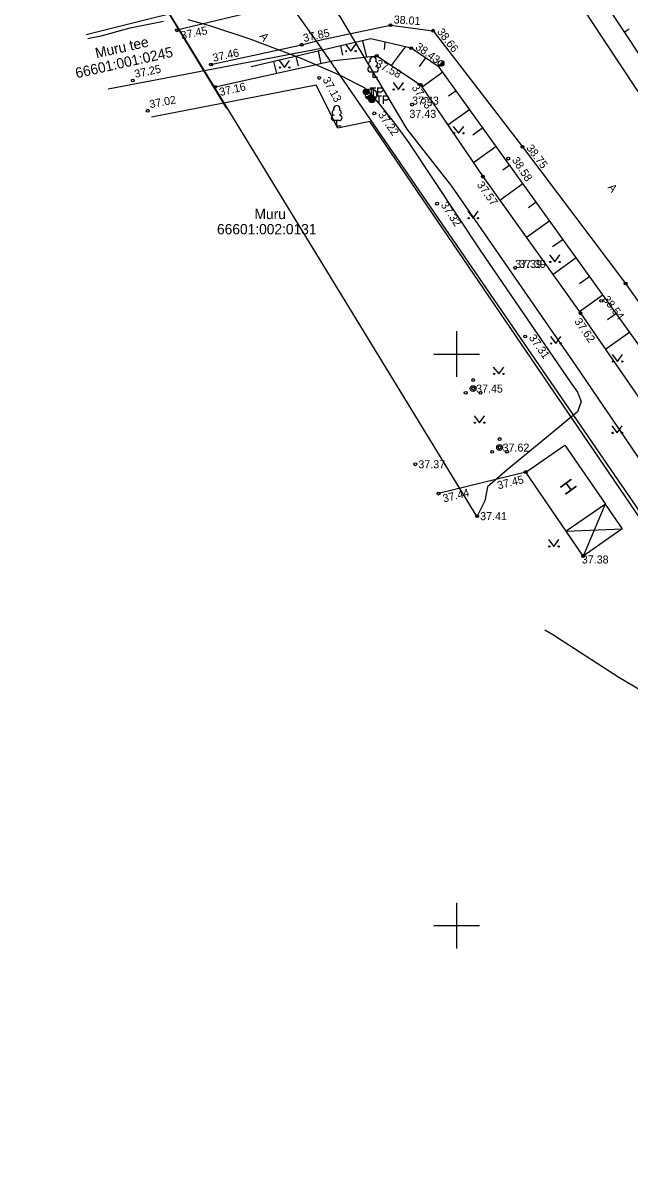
# Model space of a CAD drawing. Extents: x 627548 to 628052, y 6467984 to 6468802.
# Drawn here: x 627662.1 to 627715.2, y 6468527.7 to 6468629 of the extents above; entities that cross this region are included whole.
import ezdxf

# ---------------------------------------------------------------- set-up
doc = ezdxf.new("R2010")
doc.units = 0
for name, color, linetype in [('AED', 7, 'Continuous'), ('HALJASTUS', 7, 'Continuous'), ('HOONE', 7, 'Continuous'), ('HOONEDET', 7, 'Continuous'), ('KORGUS-EH2000', 7, 'Continuous'), ('MOOTKORG-EH2000', 7, 'Continuous'), ('MOOTMPUNKT', 7, 'Continuous'), ('MPOHULIIN', 7, 'Continuous'), ('PIIR', 7, 'Continuous'), ('POST', 7, 'Continuous'), ('PUU', 7, 'Continuous'), ('RELJEEF', 7, 'Continuous'), ('SIKAEV', 7, 'Continuous'), ('SIOHULIIN', 7, 'Continuous'), ('SITRASS', 7, 'Continuous'), ('TEE', 7, 'Continuous'), ('VORK', 7, 'Continuous')]:
    doc.layers.add(name, color=color, linetype=linetype)

msp = doc.modelspace()

# ---------------------------------------------------------------- linework, layer by layer
at = {"layer": 'AED'}
msp.add_lwpolyline([(627706.04, 6468589.68), (627698.42, 6468587.79)], dxfattribs=at)
at = {"layer": 'HALJASTUS'}
for p, q in [((627690.28, 6468627.11), (627690.74, 6468626.5)), ((627690.74, 6468626.5), (627691.19, 6468627.11)), ((627684.48, 6468625.68), (627684.94, 6468625.07)), ((627684.94, 6468625.07), (627685.39, 6468625.68)), ((627694.44, 6468623.75), (627694.9, 6468623.15)), ((627694.9, 6468623.15), (627695.35, 6468623.75)), ((627699.71, 6468619.92), (627700.17, 6468619.32)), ((627700.17, 6468619.32), (627700.62, 6468619.92)), ((627700.98, 6468612.5), (627701.45, 6468611.89)), ((627701.45, 6468611.89), (627701.89, 6468612.5)), ((627708.12, 6468608.67), (627708.59, 6468608.06)), ((627708.59, 6468608.06), (627709.03, 6468608.67)), ((627708.21, 6468601.54), (627708.67, 6468600.93)), ((627708.67, 6468600.93), (627709.12, 6468601.54)), ((627713.6, 6468599.96), (627714.06, 6468599.35)), ((627714.06, 6468599.35), (627714.51, 6468599.96)), ((627703.21, 6468598.87), (627703.68, 6468598.26)), ((627703.68, 6468598.26), (627704.12, 6468598.87)), ((627701.53, 6468594.61), (627701.99, 6468594)), ((627701.99, 6468594), (627702.44, 6468594.61)), ((627713.58, 6468593.71), (627714.04, 6468593.1)), ((627714.04, 6468593.1), (627714.49, 6468593.71)), ((627708.03, 6468583.78), (627708.5, 6468583.17)), ((627708.5, 6468583.17), (627708.94, 6468583.78))]:
    msp.add_line(p, q, dxfattribs=at)
msp.add_lwpolyline([(627725.71, 6468571.21), (627716.57, 6468584.87), (627692.41, 6468620.36), (627689.62, 6468619.76), (627687.7, 6468623.54), (627673.32, 6468620.74)], dxfattribs=at)
for centre in [(627690.34, 6468626.5), (627691.17, 6468626.5), (627684.54, 6468625.07), (627685.37, 6468625.07), (627694.5, 6468623.15), (627695.33, 6468623.15), (627699.77, 6468619.32), (627700.6, 6468619.32), (627701.05, 6468611.89), (627701.87, 6468611.89), (627708.19, 6468608.06), (627709.01, 6468608.06), (627708.27, 6468600.93), (627709.1, 6468600.93), (627713.66, 6468599.35), (627714.49, 6468599.35), (627703.28, 6468598.26), (627704.1, 6468598.26), (627701.59, 6468594), (627702.42, 6468594), (627713.64, 6468593.1), (627714.47, 6468593.1), (627708.1, 6468583.17), (627708.93, 6468583.17)]:
    msp.add_circle(centre, 0.055, dxfattribs=at)
at = {"layer": 'HOONE'}
for points in [[(627709.47, 6468592.04), (627713.02, 6468586.87), (627709.59, 6468584.51), (627706.04, 6468589.68), (627709.47, 6468592.04)], [(627713, 6468586.86), (627714.49, 6468584.7), (627711.07, 6468582.33), (627709.59, 6468584.51)]]:
    msp.add_lwpolyline(points, dxfattribs=at)
at = {"layer": 'HOONEDET'}
for points in [[(627713, 6468586.86), (627711.07, 6468582.33)], [(627709.57, 6468584.5), (627714.49, 6468584.7)]]:
    msp.add_lwpolyline(points, dxfattribs=at)
at = {"layer": 'KORGUS-EH2000'}
for centre in [(627694.21, 6468628.78), (627675.53, 6468628.33), (627697.95, 6468628.29), (627686.44, 6468627.07), (627696.02, 6468626.76), (627693.02, 6468626.09), (627678.51, 6468625.34), (627671.68, 6468623.94), (627687.97, 6468624.16), (627678.88, 6468623.38), (627696.85, 6468623.56), (627672.98, 6468621.29), (627692.8, 6468621.06), (627705.76, 6468618.13), (627704.52, 6468617.1), (627702.29, 6468615.53), (627698.29, 6468613.16), (627714.78, 6468606.18), (627712.65, 6468604.66), (627710.84, 6468603.57), (627705.99, 6468601.54), (627701.44, 6468596.98), (627703.76, 6468591.82), (627696.39, 6468590.36), (627706.04, 6468589.68), (627698.42, 6468587.79), (627701.8, 6468585.82), (627711.07, 6468582.33)]:
    msp.add_circle(centre, 0.125, dxfattribs=at)
at = {"layer": 'MOOTMPUNKT'}
for centre in [(627696.1, 6468621.83), (627705.12, 6468607.54)]:
    msp.add_circle(centre, 0.125, dxfattribs=at)
at = {"layer": 'MPOHULIIN'}
msp.add_lwpolyline([(627679.91, 6468621.5), (627673.06, 6468632.74), (627672.71, 6468633.31)], dxfattribs=at)
at = {"layer": 'PIIR'}
for p, q in [((627667.6, 6468627.96), (627684.35, 6468632.16)), ((627688.18, 6468626.77), (627684.35, 6468632.16)), ((627669.51, 6468623.2), (627688.18, 6468626.77)), ((627746.88, 6468541.25), (627688.18, 6468626.77))]:
    msp.add_line(p, q, dxfattribs=at)
at = {"layer": 'POST'}
for p, q in [((627698.47, 6468625.26), (627698.82, 6468625.62)), ((627692.45, 6468623.3), (627692.92, 6468623.3)), ((627692.69, 6468623.3), (627692.69, 6468622.6)), ((627693.09, 6468623.3), (627693.09, 6468622.6)), ((627692.95, 6468622.6), (627693.42, 6468622.6)), ((627693.18, 6468622.6), (627693.18, 6468621.9)), ((627693.58, 6468622.6), (627693.58, 6468621.9))]:
    msp.add_line(p, q, dxfattribs=at)
for points in [[(627693.09, 6468623.3), (627693.39, 6468623.3), (627693.49, 6468623.27), (627693.52, 6468623.23), (627693.55, 6468623.17), (627693.55, 6468623.07), (627693.52, 6468623), (627693.49, 6468622.97), (627693.39, 6468622.93), (627693.09, 6468622.93)], [(627693.58, 6468622.6), (627693.88, 6468622.6), (627693.98, 6468622.57), (627694.02, 6468622.53), (627694.05, 6468622.47), (627694.05, 6468622.37), (627694.02, 6468622.3), (627693.98, 6468622.27), (627693.88, 6468622.23), (627693.58, 6468622.23)]]:
    msp.add_lwpolyline(points, dxfattribs=at)
for centre, radius in [((627698.64, 6468625.44), 0.25), ((627692.09, 6468622.95), 0.25), ((627692.09, 6468622.95), 0.225), ((627692.09, 6468622.95), 0.2), ((627692.09, 6468622.95), 0.175), ((627692.09, 6468622.95), 0.15), ((627692.09, 6468622.95), 0.125), ((627692.09, 6468622.95), 0.1), ((627692.09, 6468622.95), 0.075), ((627692.09, 6468622.95), 0.05), ((627692.09, 6468622.95), 0.025), ((627692.59, 6468622.25), 0.25), ((627692.59, 6468622.25), 0.225), ((627692.59, 6468622.25), 0.2), ((627692.59, 6468622.25), 0.175), ((627692.59, 6468622.25), 0.15), ((627692.59, 6468622.25), 0.125), ((627692.59, 6468622.25), 0.1), ((627692.59, 6468622.25), 0.075), ((627692.59, 6468622.25), 0.05), ((627692.59, 6468622.25), 0.025)]:
    msp.add_circle(centre, radius, dxfattribs=at)
for radius, start, end in [(0.225, 224.8541, 45.0356), (0.2, 224.8427, 45.047), (0.175, 224.8281, 45.0616), (0.15, 224.8087, 45.081), (0.125, 224.7814, 45.1083), (0.1, 224.7406, 45.1491), (0.075, 224.6725, 45.2172), (0.05, 224.5363, 45.3534), (0.025, 224.1278, 45.7619)]:
    msp.add_arc((627698.64, 6468625.44), radius, start, end, dxfattribs=at)
at = {"layer": 'PUU'}
for p, q in [((627692.93, 6468624.68), (627692.45, 6468624.68)), ((627692.69, 6468624.21), (627692.69, 6468624.68)), ((627693.07, 6468624.21), (627692.69, 6468624.21)), ((627689.75, 6468620.43), (627689.27, 6468620.43)), ((627689.51, 6468619.95), (627689.51, 6468620.43)), ((627689.89, 6468619.95), (627689.51, 6468619.95))]:
    msp.add_line(p, q, dxfattribs=at)
for centre, radius in [((627701.44, 6468597.73), 0.125), ((627700.79, 6468596.61), 0.125), ((627701.44, 6468596.98), 0.25), ((627702.09, 6468596.61), 0.125), ((627703.76, 6468592.57), 0.125), ((627703.11, 6468591.45), 0.125), ((627703.76, 6468591.82), 0.25), ((627704.41, 6468591.45), 0.125)]:
    msp.add_circle(centre, radius, dxfattribs=at)
for centre, radius, start, end in [((627692.69, 6468625.73), 0.277, 332.5799, 207.4201), ((627692.46, 6468624.92), 0.238, 90.0016, 269.3953), ((627692.52, 6468625.38), 0.233, 109.0217, 253.1415), ((627692.86, 6468625.38), 0.233, 286.8508, 70.9859), ((627692.93, 6468624.92), 0.238, 270.6047, 89.9984), ((627689.51, 6468621.47), 0.277, 332.5799, 207.4201), ((627689.27, 6468620.67), 0.238, 90.0016, 269.3953), ((627689.34, 6468621.13), 0.233, 109.0217, 253.1415), ((627689.68, 6468621.13), 0.233, 286.8508, 70.9859), ((627689.74, 6468620.67), 0.238, 270.6047, 89.9984)]:
    msp.add_arc(centre, radius, start, end, dxfattribs=at)
at = {"layer": 'RELJEEF'}
for p, q in [((627714.66, 6468628.17), (627715.08, 6468628.45)), ((627689.83, 6468626.96), (627690.01, 6468626.16)), ((627691.77, 6468627.41), (627692.11, 6468625.99)), ((627693.73, 6468627.29), (627693.65, 6468626.65)), ((627695.5, 6468626.88), (627694.28, 6468625.26)), ((627685.93, 6468626.05), (627686.13, 6468625.22)), ((627687.88, 6468626.5), (627688.13, 6468625.43)), ((627697.28, 6468625.91), (627696.71, 6468625.16)), ((627683.99, 6468625.59), (627684.23, 6468624.56)), ((627698.8, 6468624.66), (627696.99, 6468623.36)), ((627699.97, 6468623.03), (627699.3, 6468622.56)), ((627701.14, 6468621.41), (627699.23, 6468620.04)), ((627702.3, 6468619.79), (627701.43, 6468619.16)), ((627703.47, 6468618.16), (627701.48, 6468616.73)), ((627704.64, 6468616.54), (627704.03, 6468616.1)), ((627705.8, 6468614.91), (627703.77, 6468613.45)), ((627706.97, 6468613.29), (627706.3, 6468612.8)), ((627708.14, 6468611.66), (627706.1, 6468610.2)), ((627709.31, 6468610.04), (627708.39, 6468609.39)), ((627710.47, 6468608.42), (627708.43, 6468606.95)), ((627711.64, 6468606.79), (627710.75, 6468606.15)), ((627712.81, 6468605.17), (627710.75, 6468603.69)), ((627713.97, 6468603.54), (627713.2, 6468602.99)), ((627715.14, 6468601.92), (627713.03, 6468600.4))]:
    msp.add_line(p, q, dxfattribs=at)
for points in [[(627702.92, 6468655.93), (627699.82, 6468652.79), (627699.86, 6468650.45), (627717.17, 6468624.41), (627735.28, 6468598.51), (627755.39, 6468570.76), (627765.75, 6468554.05), (627767.4, 6468553.34), (627769.66, 6468554.26)], [(627728.65, 6468569.5), (627732.37, 6468572.47), (627735.08, 6468574.22), (627734.42, 6468576.31), (627726.29, 6468586.4), (627698.48, 6468625.1), (627696.02, 6468626.76), (627692.48, 6468627.58), (627682.04, 6468625.13)], [(627678.88, 6468623.38), (627689.28, 6468625.68), (627693.02, 6468626.09), (627696.85, 6468623.56), (627702.29, 6468615.53), (627710.84, 6468603.57), (627720.65, 6468589.36), (627731.9, 6468575.32), (627731.52, 6468573.22), (627728.65, 6468569.5)]]:
    msp.add_lwpolyline(points, dxfattribs=at)
at = {"layer": 'SIKAEV'}
for p, q in [((627692.51, 6468622.71), (627692.1, 6468622.44)), ((627692.51, 6468623.21), (627692.51, 6468622.71)), ((627692.51, 6468622.71), (627692.93, 6468622.44))]:
    msp.add_line(p, q, dxfattribs=at)
msp.add_circle((627692.51, 6468622.71), 0.5, dxfattribs=at)
for radius in [0.05, 0.475, 0.45, 0.425, 0.4, 0.375, 0.35, 0.325, 0.3, 0.275, 0.25, 0.225, 0.2, 0.175, 0.15, 0.125, 0.1, 0.075]:
    msp.add_arc((627692.51, 6468622.71), radius, 213.5305, 326.4695, dxfattribs=at)
at = {"layer": 'SIOHULIIN'}
msp.add_lwpolyline([(627673.06, 6468632.74), (627701.78, 6468585.76)], dxfattribs=at)
at = {"layer": 'SITRASS'}
for points in [[(627601.95, 6468775.67), (627611.52, 6468756.59), (627616.83, 6468745.3), (627619.18, 6468741.19), (627623.57, 6468733.68), (627630.72, 6468721.27), (627637.95, 6468708.68), (627647.64, 6468692.03), (627654.51, 6468680.48), (627661.91, 6468667.64), (627667.08, 6468659.84), (627674.13, 6468649.94), (627689.77, 6468629.54), (627695.63, 6468619.67), (627699.56, 6468614.68), (627710.37, 6468599.05), (627720.66, 6468583.91), (627729.18, 6468571.42), (627736.57, 6468559.7), (627746.58, 6468544.71), (627757.27, 6468529.07), (627768.1, 6468513.35)], [(627667.75, 6468627.6), (627667.85, 6468627.64), (627668.9, 6468627.85), (627671.44, 6468628.54), (627674.36, 6468629.13)], [(627676.49, 6468629.26), (627678.48, 6468628.73), (627681.91, 6468627.57), (627686.46, 6468625.85), (627689.88, 6468624.37), (627691.16, 6468623.71), (627691.91, 6468623.31), (627692.51, 6468622.71), (627693.31, 6468621.79), (627694.55, 6468620.19), (627695.81, 6468618.47), (627702.08, 6468609.03), (627709.62, 6468598.03), (627710.15, 6468597.28), (627710.56, 6468596.66), (627710.89, 6468595.86), (627710.56, 6468594.94), (627708.36, 6468593.11), (627704.43, 6468589.88), (627702.71, 6468588.39), (627702.47, 6468587.16), (627701.78, 6468585.76)], [(627707.71, 6468575.88), (627708.41, 6468575.46), (627714.19, 6468571.72), (627721.76, 6468567.25), (627728.8, 6468564.04), (627728.83, 6468564.07), (627734.95, 6468561.12), (627736.34, 6468560.17), (627739.82, 6468557), (627747.95, 6468544.25), (627757.22, 6468532.63), (627766.08, 6468521.03)]]:
    msp.add_lwpolyline(points, dxfattribs=at)
at = {"layer": 'TEE'}
for points in [[(627642.85, 6468701.7), (627643.65, 6468701.04), (627643.97, 6468700.89), (627645.25, 6468699.1), (627649.29, 6468692.71), (627654.27, 6468685.48), (627656.18, 6468682.4), (627657.14, 6468678.82), (627659.85, 6468674.51), (627663.53, 6468671.28), (627666.59, 6468668.11), (627670.77, 6468663.8), (627676.2, 6468657.04), (627682.03, 6468649.28), (627691.56, 6468636.22), (627691.15, 6468633.38), (627690.38, 6468632.36), (627683.7, 6468630.28), (627675.53, 6468628.33)], [(627770.95, 6468554.63), (627768.55, 6468552.92), (627764.49, 6468553.41), (627737.11, 6468593.18), (627733.84, 6468597.71), (627715.77, 6468623.14), (627708.91, 6468633.53), (627697.58, 6468649.47), (627698.48, 6468652.5), (627699.47, 6468653.84), (627702.73, 6468656.27)], [(627678.51, 6468625.34), (627686.44, 6468627.07), (627688.38, 6468627.55), (627694.21, 6468628.78), (627697.95, 6468628.29), (627705.76, 6468618.13), (627714.78, 6468606.18), (627724.5, 6468592.39), (627727.99, 6468587.23), (627755.63, 6468547.56), (627781.22, 6468509.46), (627802.36, 6468475.11), (627803.6, 6468472.53), (627802.84, 6468469.11), (627801.16, 6468467.82), (627794.97, 6468465.06)]]:
    msp.add_lwpolyline(points, dxfattribs=at)
at = {"layer": 'VORK'}
for p, q in [((627700, 6468602), (627700, 6468598)), ((627698, 6468600), (627702, 6468600)), ((627700, 6468552), (627700, 6468548)), ((627698, 6468550), (627702, 6468550))]:
    msp.add_line(p, q, dxfattribs=at)

# ---------------------------------------------------------------- texts
at = {"layer": 'HOONE'}
msp.add_text('H', height=1.2, rotation=306.1592, dxfattribs=at).set_placement((627708.95, 6468588.51))
at = {"layer": 'KORGUS-EH2000'}
for s, rotation, p in [(' 38.01', 356.4046, (627694.22, 6468628.95)), (' 37.45', 11.9253, (627675.7, 6468627.47)), (' 37.85', 12.3897, (627686.4, 6468627.24)), (' 38.66', 307.5601, (627698.09, 6468628.39)), (' 37.46', 12.3056, (627678.48, 6468625.51)), (' 38.43', 324.0089, (627696.12, 6468626.9)), (' 37.58', 332.6161, (627692.62, 6468625.31)), (' 37.25', 11.6054, (627671.64, 6468624.11)), (' 37.16', 12.75, (627679.07, 6468622.52)), (' 37.13', 298.7496, (627688.12, 6468624.24)), (' 37.63', 304.1035, (627695.89, 6468623.53)), (' 37.02', 10.6662, (627672.94, 6468621.46)), (' 37.22', 304.8123, (627692.94, 6468621.16)), (' 38.75', 307.0746, (627705.9, 6468618.23)), (' 38.58', 303.1788, (627704.66, 6468617.2)), (' 37.57', 305.5651, (627701.58, 6468615.02)), (' 37.32', 303.5169, (627698.44, 6468613.26)), (' 38.54', 307.6506, (627712.58, 6468604.98)), (' 37.62', 304.6141, (627710.12, 6468603.07)), (' 37.31', 305.1726, (627706.13, 6468601.64)), (' 37.45', 13.886, (627703.4, 6468588.1)), (' 37.44', 13.886, (627698.63, 6468586.95))]:
    msp.add_text(s, height=0.7, rotation=rotation, dxfattribs=at).set_placement(p)
for s, p in [('37.43', (627695.87, 6468620.67)), ('37.39', (627705.47, 6468607.54)), (' 37.45', (627701.44, 6468596.63)), (' 37.62', (627703.76, 6468591.47)), (' 37.37', (627696.39, 6468590.01)), (' 37.41', (627701.8, 6468585.47)), (' 37.38', (627710.69, 6468581.68))]:
    msp.add_text(s, height=0.7, dxfattribs=at).set_placement(p)
at = {"layer": 'MOOTKORG-EH2000'}
for s, p in [('37.43', (627696.1, 6468621.83)), ('37.39', (627705.12, 6468607.54))]:
    msp.add_text(s, height=0.7, dxfattribs=at).set_placement(p)
at = {"layer": 'PIIR'}
for s, p in [('66601:001:0245', (627666.76, 6468624.13)), ('Muru tee', (627668.49, 6468625.88))]:
    msp.add_text(s, height=0.9, rotation=12.6017, dxfattribs=at).set_placement(p)
for s, p in [('Muru', (627682.32, 6468611.81)), ('66601:002:0131', (627679.04, 6468610.48))]:
    msp.add_text(s, height=0.9, dxfattribs=at).set_placement(p)
at = {"layer": 'TEE'}
for rotation, p in [(308.611, (627682.72, 6468627.79)), (307.9692, (627713.18, 6468614.57))]:
    msp.add_text('A', height=0.7, rotation=rotation, dxfattribs=at).set_placement(p)

doc.saveas('drawing.dxf')
